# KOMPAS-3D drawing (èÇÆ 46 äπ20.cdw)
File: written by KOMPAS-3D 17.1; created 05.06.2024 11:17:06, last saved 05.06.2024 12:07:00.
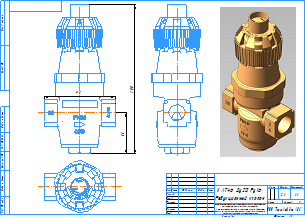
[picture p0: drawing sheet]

Sheet 1: A3, landscape

Title block, sheet 1: name: КАТ46 Ду20 Ру16 / Редукционный клапан; material: Внимание! Данный продукт является объектом авторского права ООО «Торговый Дом АДЛ». / Запрещается изменение, копирование, распространение / (в том числе путем копирования на другие сайты и ресурсы в Интернете) / или любое иное использование информации и объектов без предварительного / согласия правообладателя (ООО «Торговый Дом АДЛ»).; mass: 2,1; sheets: 1; organisation: ООО "Торговый дом АДЛ"; sheet format: A3; stored path: C:\Users\klav\Desktop\Модели\0 КАТ\КАТ 46\KOMPAS 3D\КАТ 46 Ду25.cdw

Views: Вид 1, Спереди, Проекционный вид 2
Referenced files in C:\Users\klav\Desktop\Модели\0 КАТ\КАТ 46\KOMPAS 3D\: КАТ 46 Ду25.m3d, КАТ 46 Ду20.m3d
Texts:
  Клочков АВ
  ООО АДЛ Групп
  КАТ 46 Ду20
Dimensions and other numbers on the sheet: 95; 55; 200; 1:1; 1; 2,1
